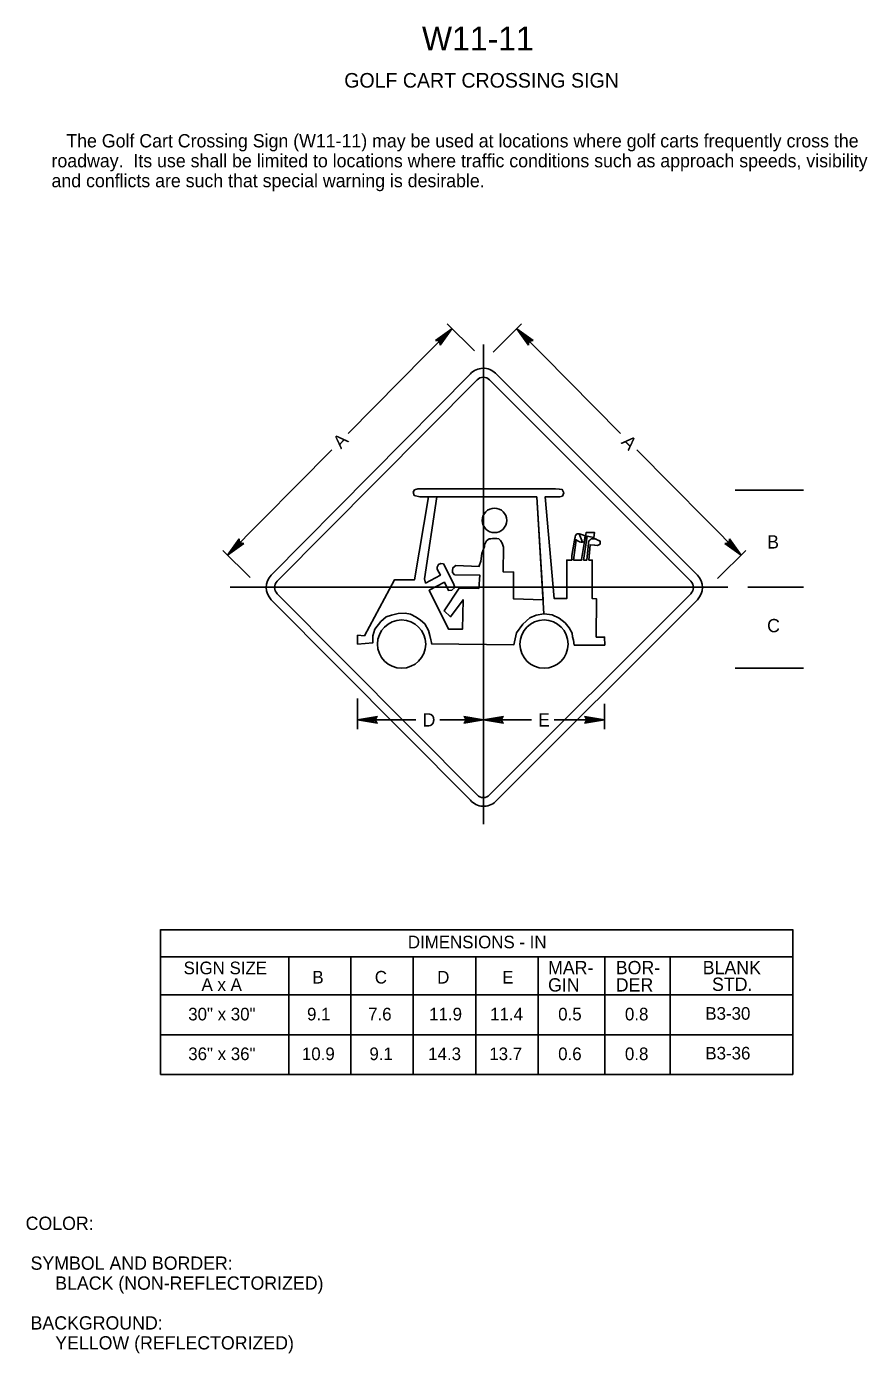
# Model space of a CAD drawing. Extents: x -0.249 to 0.289, y -0.061 to 0.281.
# Drawn here: x 0.0254 to 0.1838, y 0.0092 to 0.259 of the extents above; entities that cross this region are included whole.
import ezdxf

# ---------------------------------------------------------------- set-up
doc = ezdxf.new("R2010")
doc.units = 0
for name, color, linetype in [('1', 7, 'Continuous'), ('11', 7, 'Continuous'), ('2', 7, 'Continuous'), ('3', 7, 'Continuous')]:
    doc.layers.add(name, color=color, linetype=linetype)

# ---------------------------------------------------------------- blocks, each defined once
blk = doc.blocks.new('RARROW')
at = {"layer": '3'}
for p, q in [((-2.156, 0.28500000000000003), (-2.2665, 0.384625)), ((-2.2665, 0.384625), (0, 0)), ((0, 0), (-2.2665, -0.379125)), ((-2.156, 0.28500000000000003), (-2.075625, 0.12075)), ((0, 0), (-2.156, 0.28500000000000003)), ((-2.14975, -0.2705), (0, 0)), ((-2.075625, 0.12075), (0, 0)), ((0, 0), (-2.074, -0.108)), ((-2.2665, -0.379125), (-2.14975, -0.2705)), ((-2.074, -0.108), (-2.14975, -0.2705))]:
    blk.add_line(p, q, dxfattribs=at)

msp = doc.modelspace()

# ---------------------------------------------------------------- linework, layer by layer
at = {"layer": '1'}
for p, q in [((0.1115, 0.108875), (0.1115, 0.199125)), ((0.10108776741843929, 0.17050921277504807), (0.12150448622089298, 0.17051165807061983)), ((0.12150448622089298, 0.17051165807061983), (0.12151014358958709, 0.17051152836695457)), ((0.12285738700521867, 0.14843122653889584), (0.12151014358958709, 0.17051152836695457)), ((0.12151014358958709, 0.17051152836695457), (0.12285738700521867, 0.14843122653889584)), ((0.12872094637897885, 0.1629353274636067), (0.12855183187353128, 0.16203420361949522)), ((0.12871604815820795, 0.16291003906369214), (0.12855183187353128, 0.16203420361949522)), ((0.12972523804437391, 0.16345580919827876), (0.1294714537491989, 0.1635019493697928)), ((0.1294714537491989, 0.1635019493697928), (0.13010695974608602, 0.16195511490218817)), ((0.13010777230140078, 0.16195349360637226), (0.1294714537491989, 0.1635019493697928)), ((0.12972523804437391, 0.16345580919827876), (0.12966112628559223, 0.1634674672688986)), ((0.1303983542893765, 0.1620177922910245), (0.13058896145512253, 0.163097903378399)), ((0.13058896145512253, 0.163097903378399), (0.1304427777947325, 0.16318561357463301)), ((0.13058896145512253, 0.163097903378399), (0.1304427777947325, 0.16318561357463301)), ((0.1306878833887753, 0.16303855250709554), (0.13051410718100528, 0.16205381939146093)), ((0.12837629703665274, 0.1608735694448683), (0.12811667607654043, 0.15946555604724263)), ((0.12836420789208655, 0.16080141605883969), (0.1281169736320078, 0.15946634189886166)), ((0.12855183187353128, 0.16203420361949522), (0.12837629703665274, 0.1608735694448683)), ((0.128538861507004, 0.1619573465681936), (0.12837629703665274, 0.1608735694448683)), ((0.13010695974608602, 0.16195511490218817), (0.12981960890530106, 0.16193797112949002)), ((0.12808122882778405, 0.15907801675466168), (0.12808119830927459, 0.15857830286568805)), ((0.12808122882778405, 0.15907718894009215), (0.12808119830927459, 0.15857830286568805)), ((0.06375, 0.1535), (0.1575, 0.1535))]:
    msp.add_line(p, q, dxfattribs=at)
for points in [[(0.10108804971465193, 0.1705109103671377), (0.09848141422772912, 0.15487108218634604), (0.09471626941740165, 0.15487108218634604), (0.08903958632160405, 0.14432867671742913), (0.08776522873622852, 0.14444452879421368), (0.08776522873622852, 0.1427646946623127), (0.09060357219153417, 0.14299639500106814), (0.09060357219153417, 0.14432867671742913), (0.09100904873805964, 0.14560303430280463), (0.09210963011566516, 0.14699324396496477), (0.09315228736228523, 0.14792004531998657), (0.09413701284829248, 0.14820966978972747), (0.09541137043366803, 0.14849930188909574), (0.09674365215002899, 0.14855722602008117), (0.09772838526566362, 0.14838344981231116), (0.0987710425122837, 0.14786212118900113), (0.09958199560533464, 0.14728286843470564), (0.10039294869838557, 0.1465877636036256), (0.10108804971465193, 0.14531340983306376), (0.10137767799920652, 0.14438660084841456), (0.10155145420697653, 0.14357564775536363), (0.10172523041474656, 0.14282261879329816), (0.10166730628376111, 0.14282261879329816), (0.11719129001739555, 0.1426488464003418), (0.11765468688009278, 0.1449079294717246), (0.11887112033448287, 0.14652983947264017), (0.12020340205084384, 0.1476883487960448), (0.1213619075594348, 0.14820966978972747), (0.12285738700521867, 0.14843122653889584)], [(0.12808119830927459, 0.15857830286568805), (0.12727028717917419, 0.15857830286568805), (0.1271544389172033, 0.15857830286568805), (0.1271544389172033, 0.15133763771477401), (0.12477949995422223, 0.15133763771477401), (0.12309966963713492, 0.1705109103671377), (0.12467584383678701, 0.17049463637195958), (0.12520243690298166, 0.1704852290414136), (0.12584188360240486, 0.1704852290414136), (0.12634348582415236, 0.17062676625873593), (0.1265753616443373, 0.17122833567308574), (0.12630995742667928, 0.17185301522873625), (0.12573844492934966, 0.17195263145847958), (0.12505590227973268, 0.17196915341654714), (0.09911859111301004, 0.1719590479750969), (0.09848141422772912, 0.1717852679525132), (0.09824971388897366, 0.1713797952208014), (0.09842348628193, 0.17074261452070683), (0.09950701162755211, 0.17046294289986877), (0.10108776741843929, 0.17050921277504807)], [(0.12151014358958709, 0.17051152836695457), (0.12269418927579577, 0.15110593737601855), (0.11713335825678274, 0.15127971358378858), (0.11713335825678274, 0.15631921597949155), (0.11516389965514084, 0.15637714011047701), (0.11522182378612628, 0.16101116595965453), (0.11499012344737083, 0.16176419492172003), (0.11470049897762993, 0.16228552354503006), (0.11435294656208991, 0.16257514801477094), (0.11400539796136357, 0.16263307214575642), (0.11359991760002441, 0.16263307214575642), (0.11313651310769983, 0.16263307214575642), (0.11278896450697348, 0.16257514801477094), (0.11255726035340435, 0.16257514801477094), (0.11203593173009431, 0.16216966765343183), (0.11186215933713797, 0.16182211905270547), (0.11168838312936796, 0.16141664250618), (0.11163045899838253, 0.1611270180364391), (0.11116705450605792, 0.15979473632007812), (0.11099327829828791, 0.1583465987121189), (0.11064572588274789, 0.15747772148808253), (0.11064572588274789, 0.15736187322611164), (0.10624340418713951, 0.15753564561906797), (0.10572207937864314, 0.15713016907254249), (0.10566414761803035, 0.156550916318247), (0.10566414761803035, 0.15626128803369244), (0.10601170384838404, 0.15579788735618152), (0.11076157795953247, 0.1557399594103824), (0.11058780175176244, 0.15324917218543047), (0.10688058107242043, 0.15330709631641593), (0.10404224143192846, 0.14902062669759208), (0.10525867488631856, 0.14792004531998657), (0.1076336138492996, 0.15110593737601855), (0.10751775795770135, 0.14560303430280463), (0.1048531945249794, 0.14560303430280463), (0.10126182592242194, 0.1529016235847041), (0.10410016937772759, 0.1544076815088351), (0.10491112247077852, 0.15284369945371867), (0.10549037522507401, 0.1529016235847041), (0.10606962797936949, 0.15342295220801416), (0.10583792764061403, 0.15417598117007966), (0.10392639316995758, 0.157883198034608), (0.10346298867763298, 0.15794112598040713), (0.10299958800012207, 0.1577673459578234), (0.10276788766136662, 0.1572460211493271), (0.10276788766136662, 0.1568405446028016), (0.10305751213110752, 0.15631921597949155), (0.10334714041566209, 0.1557399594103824), (0.1005667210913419, 0.15423390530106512), (0.10033502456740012, 0.15504485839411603), (0.1027099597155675, 0.1705109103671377)], [(0.10270996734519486, 0.17051095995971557), (0.12151014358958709, 0.17051152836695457)], [(0.1284304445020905, 0.15857830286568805), (0.12889219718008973, 0.16240137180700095), (0.12917384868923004, 0.16222533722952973)], [(0.1284304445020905, 0.15857830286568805), (0.12889219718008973, 0.16240137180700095), (0.12917384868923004, 0.16222533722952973)], [(0.129278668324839, 0.1635019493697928), (0.12906597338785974, 0.1635019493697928), (0.12877634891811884, 0.16321232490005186), (0.12872094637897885, 0.1629353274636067)], [(0.1294714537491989, 0.1635019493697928), (0.12906597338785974, 0.1635019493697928), (0.12877634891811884, 0.16321232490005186), (0.12872094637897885, 0.1629353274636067)], [(0.1312514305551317, 0.16178879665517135), (0.13091363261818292, 0.15858025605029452), (0.13030740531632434, 0.15858025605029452), (0.1309775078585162, 0.163096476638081), (0.13225186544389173, 0.16280684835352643), (0.1323677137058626, 0.16379157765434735), (0.13080373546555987, 0.16379157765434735), (0.1306878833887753, 0.16303855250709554)], [(0.1312514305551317, 0.16178879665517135), (0.13091363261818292, 0.15858025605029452), (0.13030740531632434, 0.15858025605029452), (0.1309775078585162, 0.163096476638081), (0.13225186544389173, 0.16280684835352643), (0.1323677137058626, 0.16379157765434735), (0.13080373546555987, 0.16379157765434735), (0.1306878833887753, 0.16303855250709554)], [(0.1325198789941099, 0.16255699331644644), (0.13248356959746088, 0.16257514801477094), (0.13219394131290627, 0.16257514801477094), (0.13178846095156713, 0.16257514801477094), (0.13173053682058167, 0.16257514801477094), (0.13149883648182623, 0.1623434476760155), (0.1313250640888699, 0.16216966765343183), (0.13130351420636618, 0.16208348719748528)], [(0.13268198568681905, 0.16248419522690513), (0.13248356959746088, 0.16257514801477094), (0.13219394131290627, 0.16257514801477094), (0.13178846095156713, 0.16257514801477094), (0.13173053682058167, 0.16257514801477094), (0.13149883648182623, 0.1623434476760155), (0.1313250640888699, 0.16216966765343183), (0.13130351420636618, 0.16208348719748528)], [(0.13301961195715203, 0.16234914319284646), (0.13288904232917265, 0.16240137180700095), (0.13268198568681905, 0.16248419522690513)], [(0.13317867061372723, 0.16228552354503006), (0.13288904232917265, 0.16240137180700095), (0.13268198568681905, 0.16248419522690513)], [(0.13051410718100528, 0.16205381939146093), (0.1299348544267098, 0.15869415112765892), (0.1299348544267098, 0.15857830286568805), (0.1284304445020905, 0.15857830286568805)], [(0.1295562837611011, 0.16203648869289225), (0.12981900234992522, 0.16193797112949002), (0.12981960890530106, 0.16193797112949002)], [(0.1295562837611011, 0.16203648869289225), (0.12981900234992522, 0.16193797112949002), (0.13010777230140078, 0.16195349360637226)], [(0.1343371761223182, 0.14253299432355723), (0.13427925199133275, 0.14409697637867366), (0.13271526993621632, 0.14409697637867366), (0.13277319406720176, 0.15127971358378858), (0.13196224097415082, 0.15133763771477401), (0.13196250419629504, 0.15858025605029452), (0.13132740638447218, 0.15858025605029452), (0.13155676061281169, 0.16147456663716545), (0.1324024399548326, 0.16136180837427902)], [(0.1343371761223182, 0.14253299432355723), (0.13427925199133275, 0.14409697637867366), (0.13271526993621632, 0.14409697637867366), (0.13277319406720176, 0.15127971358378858), (0.13196224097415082, 0.15133763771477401), (0.13196250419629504, 0.15858025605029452), (0.13132740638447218, 0.15858025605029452), (0.13155676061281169, 0.16147456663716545), (0.1324024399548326, 0.16136180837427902)], [(0.13244890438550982, 0.1613561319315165), (0.13294697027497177, 0.16130079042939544), (0.13341037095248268, 0.16159041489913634), (0.1334682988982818, 0.1620917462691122), (0.13317867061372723, 0.16228552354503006)], [(0.13244890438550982, 0.1613561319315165), (0.13294697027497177, 0.16130079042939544), (0.13341037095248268, 0.16159041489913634), (0.1334267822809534, 0.16167244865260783)], [(0.1334682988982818, 0.1620917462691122), (0.1334682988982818, 0.16211174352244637), (0.13332557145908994, 0.1621973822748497)], [(0.12285738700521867, 0.14843122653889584), (0.12292589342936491, 0.14844137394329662), (0.12437402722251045, 0.1482676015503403), (0.12570630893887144, 0.1476304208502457), (0.1268648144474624, 0.1467615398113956), (0.1276178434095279, 0.1458347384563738), (0.1281391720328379, 0.14485000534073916), (0.1282550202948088, 0.14415490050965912), (0.12842879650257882, 0.1435177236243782), (0.12854464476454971, 0.14259092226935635), (0.1343371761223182, 0.14253299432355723)]]:
    msp.add_lwpolyline(points, dxfattribs=at)
for centre, radius in [((0.11354199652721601, 0.1660506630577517), 0.002308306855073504), ((0.09604855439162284, 0.14276469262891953), 0.004536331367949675), ((0.12286797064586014, 0.14276469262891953), 0.004536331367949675)]:
    msp.add_circle(centre, radius, dxfattribs=at)
for centre, radius, start, end in [((0.1308174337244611, 0.1625160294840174), 0.002138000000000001, 168.69006589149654, 169.3803437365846), ((0.12927867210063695, 0.16136394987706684), 0.002138, 79.69515449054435, 89.99999982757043), ((0.12934278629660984, 0.1613522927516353), 0.0021380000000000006, 59.03624518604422, 79.69515449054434), ((0.12934278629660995, 0.16135229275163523), 0.0021380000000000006, 59.03624518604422, 79.69515449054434), ((0.1334760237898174, 0.1644692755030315), 0.0021379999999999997, 243.43495100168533, 248.1985927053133), ((0.13222558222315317, 0.16036405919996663), 0.0021380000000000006, 59.03624579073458, 68.1985920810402), ((0.1262619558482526, 0.16119071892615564), 0.002138, 349.5085220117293, 351.46923359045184), ((0.1306532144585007, 0.16164019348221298), 0.0021379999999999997, 169.3803437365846, 171.4692335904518), ((0.13030699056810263, 0.16403835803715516), 0.0021380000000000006, 237.99461942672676, 249.4439564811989), ((0.13030699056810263, 0.16403835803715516), 0.0021380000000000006, 237.99461942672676, 249.4439564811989), ((0.12981960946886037, 0.16407596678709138), 0.002138, 270.00000014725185, 285.70572703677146), ((0.12981960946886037, 0.16407596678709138), 0.002138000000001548, 270.00000019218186, 285.70572703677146), ((0.1333776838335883, 0.1615649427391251), 0.002138, 165.96375439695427, 173.99000464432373), ((0.13337768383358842, 0.16156494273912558), 0.002138, 165.96375439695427, 173.99000464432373), ((0.13268501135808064, 0.16348105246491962), 0.0021380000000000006, 262.4053574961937, 263.6598087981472), ((0.13268501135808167, 0.16348105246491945), 0.0021380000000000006, 262.4053574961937, 263.6598087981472), ((0.13133030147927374, 0.16209174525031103), 0.002137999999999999, 348.6900660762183, 359.9999992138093), ((0.13021923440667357, 0.15907703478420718), 0.002138, 169.5085220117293, 179.99600206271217), ((0.13021923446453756, 0.15907786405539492), 0.002138, 169.5525992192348, 179.99600206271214)]:
    msp.add_arc(centre, radius, start, end, dxfattribs=at)
at = {"layer": '11'}
for p, q in [((0.07150000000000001, 0.15575), (0.109, 0.193625)), ((0.072625, 0.154625), (0.11025, 0.1925)), ((0.112625, 0.1925), (0.1505, 0.154625)), ((0.11375, 0.19375), (0.15175, 0.15575)), ((0.109, 0.113375), (0.07150000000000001, 0.151125)), ((0.11025, 0.114375), (0.072625, 0.15225)), ((0.1505, 0.15225), (0.112625, 0.114375)), ((0.15175, 0.151125), (0.11375, 0.113125))]:
    msp.add_line(p, q, dxfattribs=at)
for centre, radius, start, end in [((0.11143695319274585, 0.19133327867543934), 0.003345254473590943, 46.25569722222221, 136.75917222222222), ((0.1114375, 0.1913228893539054), 0.0016720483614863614, 44.748261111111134, 135.25173611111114), ((0.07381557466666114, 0.15343750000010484), 0.003272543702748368, 135.0380638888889, 224.96193333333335), ((0.1493972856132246, 0.1534375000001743), 0.00329892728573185, 315.49388055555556, 44.50611944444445), ((0.07381407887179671, 0.1534375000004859), 0.0016804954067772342, 135.0380638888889, 224.96193333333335), ((0.1492918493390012, 0.15343749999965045), 0.001694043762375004, 315.49388055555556, 44.50611944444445), ((0.11149657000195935, 0.11555983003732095), 0.0033175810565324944, 221.19023055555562, 312.7841944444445), ((0.1114374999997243, 0.11552991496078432), 0.001656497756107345, 224.2030166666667, 315.7969805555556)]:
    msp.add_arc(centre, radius, start, end, dxfattribs=at)
at = {"layer": '3'}
for p, q in [((0.10978235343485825, 0.19793164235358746), (0.10464208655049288, 0.20302668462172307)), ((0.1132754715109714, 0.19774115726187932), (0.11860791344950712, 0.20302668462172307)), ((0.08598308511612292, 0.18242643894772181), (0.10552986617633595, 0.20214671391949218)), ((0.13726691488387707, 0.18242643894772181), (0.11772013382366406, 0.20214671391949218)), ((0.08290319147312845, 0.1793192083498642), (0.06327986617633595, 0.1595217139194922)), ((0.14034680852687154, 0.1793192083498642), (0.15997013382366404, 0.1595217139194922)), ((0.15887500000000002, 0.17175), (0.17175, 0.17175)), ((0.06753234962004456, 0.15530664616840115), (0.06239208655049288, 0.16040168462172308)), ((0.15552547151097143, 0.15511615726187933), (0.16085791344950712, 0.16040168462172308)), ((0.16125, 0.1535), (0.17175, 0.1535)), ((0.15887500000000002, 0.13825), (0.17175, 0.13825)), ((0.08775000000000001, 0.12675), (0.08775000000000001, 0.1325)), ((0.13425, 0.12675), (0.13425, 0.1315)), ((0.08775000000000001, 0.1285), (0.09875, 0.1285)), ((0.10325000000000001, 0.1285), (0.1115, 0.1285)), ((0.1115, 0.1285), (0.1205, 0.1285)), ((0.12475, 0.1285), (0.13425, 0.1285)), ((0.050625, 0.08902174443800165), (0.050625, 0.061771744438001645)), ((0.050625, 0.089), (0.16975, 0.089)), ((0.16975, 0.08902174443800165), (0.16975, 0.061771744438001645)), ((0.16975, 0.083875), (0.050625, 0.083875)), ((0.07481300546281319, 0.0839838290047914), (0.07481300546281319, 0.061771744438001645)), ((0.08650000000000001, 0.08389674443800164), (0.08650000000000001, 0.061771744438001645)), ((0.09825, 0.08389674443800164), (0.09825, 0.061771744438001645)), ((0.11, 0.08389674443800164), (0.11, 0.061771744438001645)), ((0.12178835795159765, 0.08395422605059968), (0.12178835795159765, 0.061771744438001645)), ((0.13430529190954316, 0.08395422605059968), (0.13430529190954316, 0.061771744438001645)), ((0.14661630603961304, 0.08395422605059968), (0.14661630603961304, 0.061771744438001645)), ((0.050625, 0.07675), (0.16975, 0.07675)), ((0.050625, 0.06925), (0.16975, 0.06925)), ((0.050625, 0.061771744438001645), (0.16975, 0.061771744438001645))]:
    msp.add_line(p, q, dxfattribs=at)

# ---------------------------------------------------------------- block references
for p, xscale, yscale, rotation in [((0.1055, 0.202125), 0.001654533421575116, 0.0016366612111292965, 45.25314611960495), ((0.11775000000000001, 0.202125), 0.0016545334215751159, 0.001636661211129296, 134.7468538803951), ((0.06325, 0.1595), 0.0016545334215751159, 0.0016366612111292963, -134.74685388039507), ((0.16, 0.1595), 0.0016545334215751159, 0.0016366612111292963, -45.25314611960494), ((0.08775000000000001, 0.1285), 0.0016545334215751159, 0.0016366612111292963, 180), ((0.1115, 0.1285), 0.0016545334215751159, 0.0016366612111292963, 180)]:
    msp.add_blockref('RARROW', p, dxfattribs=dict(at, xscale=xscale, yscale=yscale, rotation=rotation))
at = {"layer": '3', "xscale": 0.0016545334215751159, "yscale": 0.0016366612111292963}
for p in [(0.1115, 0.1285), (0.13425, 0.1285)]:
    msp.add_blockref('RARROW', p, dxfattribs=at)

# ---------------------------------------------------------------- texts
at = {"layer": '1'}
for s, height, p in [('W11-11', 0.0045000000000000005, (0.099875, 0.2545)), ('GOLF CART CROSSING SIGN', 0.00275025, (0.08525, 0.2475)), ('D', 0.0024997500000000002, (0.1, 0.12725)), ('E', 0.0024997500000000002, (0.12175, 0.12725)), ('COLOR:', 0.0024997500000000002, (0.02525, 0.032499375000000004)), (' SYMBOL AND BORDER:', 0.0024997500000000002, (0.02525, 0.024999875)), ('      BLACK (NON-REFLECTORIZED)', 0.0024997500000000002, (0.02525, 0.021250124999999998)), (' BACKGROUND:', 0.0024997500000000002, (0.02525, 0.013750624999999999)), ('      YELLOW (REFLECTORIZED)', 0.0024997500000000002, (0.02525, 0.010000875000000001))]:
    msp.add_text(s, height=height, dxfattribs=at).set_placement(p)
at = {"layer": '2'}
for s, p in [('   The Golf Cart Crossing Sign (W11-11) may be used at locations where golf carts frequently cross the', (0.030125, 0.23625000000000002)), ('roadway.  Its use shall be limited to locations where traffic conditions such as approach speeds, visibility', (0.030125, 0.2325)), ('and conflicts are such that special warning is desirable.', (0.030125, 0.22875))]:
    msp.add_text(s, height=0.0024997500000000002, dxfattribs=at).set_placement(p)
at = {"layer": '3'}
for rotation, p in [(45.253147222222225, (0.084625, 0.179375)), (314.7468527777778, (0.13725, 0.180625))]:
    msp.add_text('A', height=0.0024997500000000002, rotation=rotation, dxfattribs=at).set_placement(p)
for s, height, p in [('B', 0.0024997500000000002, (0.164875, 0.16075)), ('C', 0.0024997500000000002, (0.164875, 0.145)), ('DIMENSIONS - IN', 0.0023752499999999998, (0.09722979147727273, 0.0855)), ('SIGN SIZE', 0.0023752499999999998, (0.055, 0.080625)), ('MAR-', 0.0024997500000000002, (0.123625, 0.080625)), ('BOR-', 0.0024997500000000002, (0.136375, 0.080625)), ('BLANK', 0.0024997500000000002, (0.15275, 0.080625)), ('B', 0.0023752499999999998, (0.07925, 0.078875)), ('C', 0.0023752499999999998, (0.091, 0.078875)), ('D', 0.0023752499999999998, (0.10275000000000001, 0.078875)), ('E', 0.0023752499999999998, (0.115, 0.078875)), ('STD.', 0.0024997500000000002, (0.1545, 0.0775)), ('A x A', 0.0023752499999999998, (0.058375, 0.0775)), ('GIN', 0.0024997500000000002, (0.123625, 0.077375)), ('DER', 0.0024997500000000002, (0.136375, 0.077375)), ('30" x 30"', 0.0023752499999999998, (0.05587041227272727, 0.071937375)), ('9.1', 0.0023752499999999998, (0.07824039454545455, 0.071937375)), ('7.6', 0.0023752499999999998, (0.0897435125, 0.071937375)), ('11.9', 0.0023752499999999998, (0.10124327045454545, 0.071937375)), ('11.4', 0.0023752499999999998, (0.11272815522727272, 0.071937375)), ('0.5', 0.0023752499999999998, (0.12553378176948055, 0.071937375)), ('0.8', 0.0023752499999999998, (0.1381055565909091, 0.071937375)), ('B3-30', 0.0023752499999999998, (0.15324638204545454, 0.072062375)), ('36" x 36"', 0.0023752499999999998, (0.05587041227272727, 0.06445911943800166)), ('10.9', 0.0023752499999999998, (0.07727733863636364, 0.06445911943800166)), ('9.1', 0.0023752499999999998, (0.08999039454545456, 0.06445911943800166)), ('14.3', 0.0023752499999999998, (0.10105828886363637, 0.06445911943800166)), ('13.7', 0.0023752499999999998, (0.11255936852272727, 0.06445911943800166)), ('0.6', 0.0023752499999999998, (0.12553090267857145, 0.06445911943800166)), ('0.8', 0.0023752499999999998, (0.1381055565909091, 0.06445911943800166)), ('B3-36', 0.0023752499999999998, (0.15325142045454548, 0.06458411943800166))]:
    msp.add_text(s, height=height, dxfattribs=at).set_placement(p)

doc.saveas('drawing.dxf')
